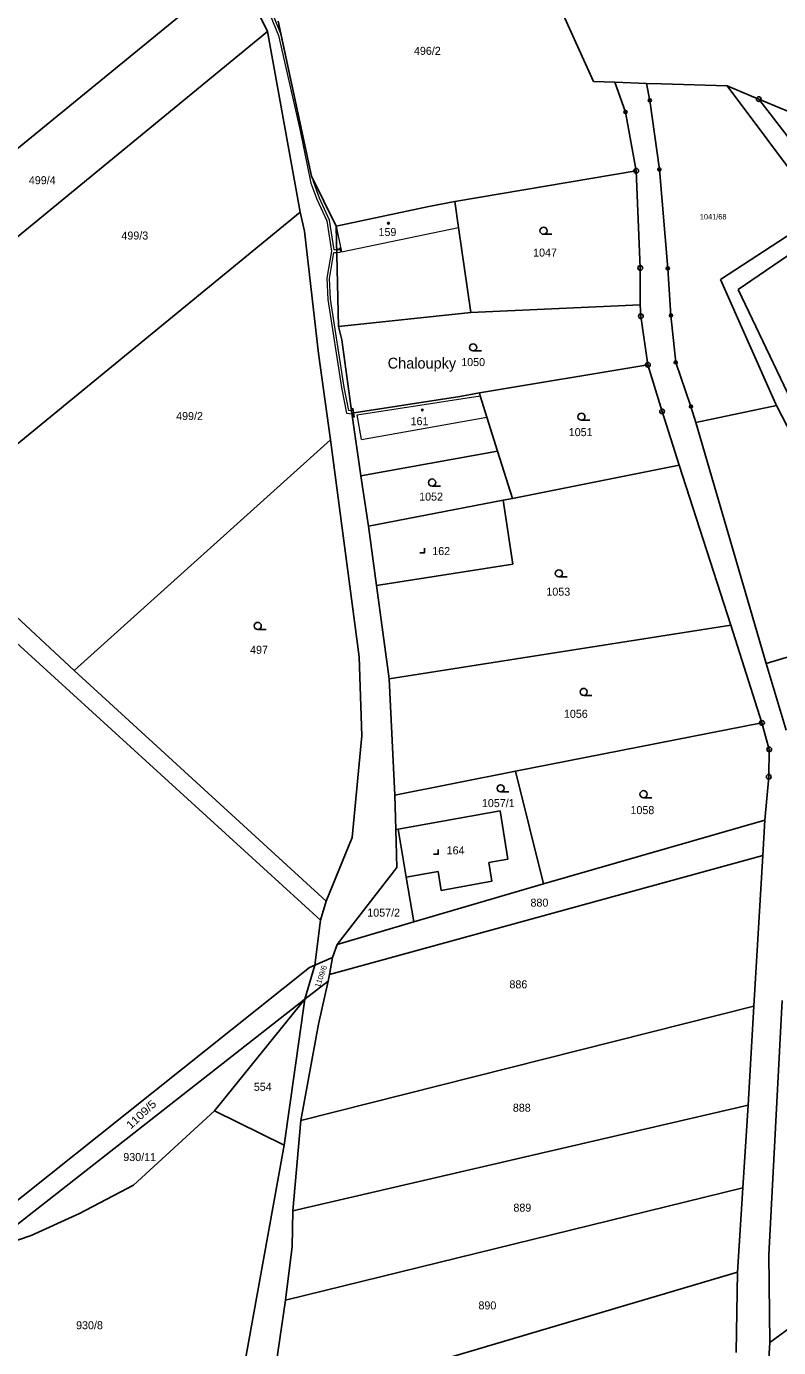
# Model space of a CAD drawing. Extents: x -694609 to -690140, y -1033292 to -1029794.
# Drawn here: x -691085 to -690925.2, y -1031744.2 to -1031463.5 of the extents above; entities that cross this region are included whole.
import ezdxf
from ezdxf.enums import TextEntityAlignment as Align

# ---------------------------------------------------------------- set-up
doc = ezdxf.new("R2010")
doc.units = 0
doc.header["$LTSCALE"] = 0.68
for name, color, linetype, lineweight in [('1', 7, 'Continuous', 25), ('13', 7, 'Continuous', 13), ('3', 7, 'Continuous', 25), ('4', 7, 'Continuous', 13), ('5', 7, 'Continuous', 25), ('7', 7, 'Continuous', 13), ('8', 7, 'Continuous', 25)]:
    doc.layers.add(name, color=color, linetype=linetype, lineweight=lineweight)
doc.layers.add('2', color=7, linetype='Continuous')

msp = doc.modelspace()

# ---------------------------------------------------------------- linework, layer by layer
at = {"layer": '1'}
for p, q in [((-690977.69, -1031446.05), (-690964.56, -1031475.26)), ((-691040.21, -1031451.34), (-691144, -1031536.13)), ((-691033.73, -1031464.62), (-691040.21, -1031451.34)), ((-691024.42, -1031495.33), (-691031.48, -1031462.45)), ((-691033.73, -1031464.62), (-691133.16, -1031546.19)), ((-691026.82, -1031502.98), (-691033.73, -1031464.62)), ((-690964.56, -1031475.26), (-690959.98, -1031475.41)), ((-690957.73, -1031481.73), (-690959.98, -1031475.41)), ((-690959.98, -1031475.41), (-690953.24, -1031475.63)), ((-690952.56, -1031479.25), (-690953.24, -1031475.63)), ((-690953.24, -1031475.63), (-690950.05, -1031475.73)), ((-690950.05, -1031475.73), (-690936.17, -1031476.19)), ((-690915.94, -1031503.17), (-690936.17, -1031476.19)), ((-690936.17, -1031476.19), (-690931, -1031478.34)), ((-690950.54, -1031493.95), (-690952.56, -1031479.25)), ((-690931, -1031478.34), (-690929.43, -1031478.99)), ((-690877.44, -1031546.54), (-690929.43, -1031478.99)), ((-690929.43, -1031478.99), (-690915.12, -1031484.95)), ((-690955.45, -1031494.2), (-690957.73, -1031481.73)), ((-691019.19, -1031506), (-691024.42, -1031495.33)), ((-690993.96, -1031500.75), (-690955.45, -1031494.2)), ((-690955.45, -1031494.2), (-690954.61, -1031514.86)), ((-690948.75, -1031514.94), (-690950.54, -1031493.95)), ((-690999.53, -1031501.76), (-691019.19, -1031506)), ((-690999.53, -1031501.76), (-690993.96, -1031500.75)), ((-690993.17, -1031506.24), (-690993.96, -1031500.75)), ((-691026.82, -1031502.98), (-691108.02, -1031569.55)), ((-691026.82, -1031502.98), (-691025.88, -1031507.05)), ((-690937.57, -1031517.29), (-690915.94, -1031503.17)), ((-691025.88, -1031507.05), (-691022.92, -1031533.04)), ((-691019.19, -1031506), (-691018.67, -1031527.31)), ((-690990.57, -1031524.34), (-690993.17, -1031506.24)), ((-690933.81, -1031519.44), (-690913.87, -1031505.78)), ((-690954.61, -1031514.86), (-690954.58, -1031522.71)), ((-690948.08, -1031524.92), (-690948.75, -1031514.94)), ((-690925.79, -1031543.77), (-690937.57, -1031517.29)), ((-690918.48, -1031551.64), (-690933.81, -1031519.44)), ((-691018.67, -1031527.31), (-690990.57, -1031524.34)), ((-690990.57, -1031524.34), (-690954.58, -1031522.71)), ((-690954.58, -1031522.71), (-690954.47, -1031525.12)), ((-691018.67, -1031527.31), (-691017.94, -1031530.11)), ((-690954.47, -1031525.12), (-690952.96, -1031535.41)), ((-690947.07, -1031534.91), (-690948.08, -1031524.92)), ((-691017.94, -1031530.11), (-691015.86, -1031545.71)), ((-691022.92, -1031533.04), (-691020.4, -1031551.35)), ((-690988.76, -1031541.42), (-690952.96, -1031535.41)), ((-690952.96, -1031535.41), (-690949.96, -1031545.32)), ((-690943.82, -1031544.27), (-690947.07, -1031534.91)), ((-690992.9, -1031542.17), (-690988.76, -1031541.42)), ((-690988.76, -1031541.42), (-690988.57, -1031542.02)), ((-691015.86, -1031545.71), (-690992.9, -1031542.17)), ((-690988.57, -1031542.02), (-690987.15, -1031546.55)), ((-690943.82, -1031544.27), (-690942.82, -1031547.7)), ((-690942.82, -1031547.7), (-690925.64, -1031544.06)), ((-690925.64, -1031544.06), (-690925.79, -1031543.77)), ((-690921.19, -1031552.75), (-690925.64, -1031544.06)), ((-691015.86, -1031545.71), (-691013.95, -1031559.04)), ((-690987.15, -1031546.55), (-690984.89, -1031553.76)), ((-690949.96, -1031545.32), (-690946.34, -1031556.72)), ((-690927.87, -1031598.9), (-690942.82, -1031547.7)), ((-691020.4, -1031551.35), (-691074.82, -1031600.38)), ((-691020.4, -1031551.35), (-691014.32, -1031597.48)), ((-690981.75, -1031563.8), (-690946.34, -1031556.72)), ((-690946.34, -1031556.72), (-690935.35, -1031590.74)), ((-690983.74, -1031564.19), (-690981.75, -1031563.8)), ((-691012.3, -1031569.74), (-690983.74, -1031564.19)), ((-690981.63, -1031577.77), (-690983.74, -1031564.19)), ((-691074.82, -1031600.38), (-691108.02, -1031569.55)), ((-691010.61, -1031582.3), (-691012.3, -1031569.74)), ((-691010.61, -1031582.3), (-690981.63, -1031577.77)), ((-691007.93, -1031602.18), (-691010.61, -1031582.3)), ((-691022.5, -1031653.42), (-691091.18, -1031590.8)), ((-691007.93, -1031602.18), (-690935.35, -1031590.74)), ((-690935.35, -1031590.74), (-690928.74, -1031611.51)), ((-690927.87, -1031598.9), (-690896.83, -1031589.54)), ((-691014.32, -1031597.48), (-691013.71, -1031614.26)), ((-691021.3, -1031649.41), (-691074.82, -1031600.38)), ((-690923.64, -1031613.04), (-690927.87, -1031598.9)), ((-691006.7, -1031626.85), (-691007.93, -1031602.18)), ((-690981.09, -1031621.79), (-690928.74, -1031611.51)), ((-690928.74, -1031611.51), (-690927.19, -1031617.14)), ((-691013.71, -1031614.26), (-691015.8, -1031635.84)), ((-690927.19, -1031617.14), (-690927.29, -1031622.97)), ((-691006.7, -1031626.85), (-690981.09, -1031621.79)), ((-690981.09, -1031621.79), (-690975.11, -1031645.73)), ((-690927.29, -1031622.97), (-690928.12, -1031632.2)), ((-691006.49, -1031634.14), (-691006.7, -1031626.85)), ((-691006.02, -1031634.06), (-690984.34, -1031630.19)), ((-690984.34, -1031630.19), (-690982.71, -1031640.46)), ((-691006.49, -1031634.14), (-691006.02, -1031634.06)), ((-691006.26, -1031642.21), (-691006.49, -1031634.14)), ((-691006.02, -1031634.06), (-691004.28, -1031644.3)), ((-690975.11, -1031645.73), (-690928.12, -1031632.2)), ((-690928.58, -1031639.67), (-690928.12, -1031632.2)), ((-691015.8, -1031635.84), (-691021.3, -1031649.41)), ((-691020.6, -1031664.96), (-690928.58, -1031639.67)), ((-690930.5, -1031671.7), (-690928.58, -1031639.67)), ((-691019, -1031658.56), (-691006.26, -1031642.21)), ((-690986.76, -1031641.18), (-690982.71, -1031640.46)), ((-690986.76, -1031641.18), (-690986.11, -1031645.17)), ((-691004.28, -1031644.3), (-690997.54, -1031643.1)), ((-691004.28, -1031644.3), (-691002.69, -1031653.75)), ((-690997.54, -1031643.1), (-690996.89, -1031647.09)), ((-690996.89, -1031647.09), (-690986.11, -1031645.17)), ((-691002.69, -1031653.75), (-690975.11, -1031645.73)), ((-691022.5, -1031653.42), (-691021.3, -1031649.41)), ((-691023.69, -1031662.97), (-691022.5, -1031653.42)), ((-691019, -1031658.56), (-691002.69, -1031653.75)), ((-691019.93, -1031661.33), (-691019, -1031658.56)), ((-691019.93, -1031661.33), (-691023.69, -1031662.97)), ((-691020.6, -1031664.96), (-691019.93, -1031661.33)), ((-691101.39, -1031724.53), (-691024.87, -1031663.48)), ((-691025.84, -1031670.19), (-691023.69, -1031662.97)), ((-691023.69, -1031662.97), (-691024.87, -1031663.48)), ((-691020.87, -1031666.39), (-691020.6, -1031664.96)), ((-691025.84, -1031670.19), (-691020.87, -1031666.39)), ((-691022.93, -1031675.53), (-691020.87, -1031666.39)), ((-691093.45, -1031723.2), (-691025.84, -1031670.19)), ((-691045, -1031693.97), (-691025.84, -1031670.19)), ((-691030.2, -1031701.21), (-691025.84, -1031670.19)), ((-690927.26, -1031724.52), (-690924.48, -1031670.48)), ((-690930.5, -1031671.7), (-691026.71, -1031696.02)), ((-690931.7, -1031692.76), (-690930.5, -1031671.7)), ((-691026.71, -1031696.02), (-691022.93, -1031675.53)), ((-691028.39, -1031715.21), (-690931.7, -1031692.76)), ((-690932.82, -1031710.26), (-690931.7, -1031692.76)), ((-691045, -1031693.97), (-691062.19, -1031709.74)), ((-691030.2, -1031701.21), (-691045, -1031693.97)), ((-691028.39, -1031715.21), (-691026.71, -1031696.02)), ((-691041.79, -1031765.13), (-691030.2, -1031701.21)), ((-691062.19, -1031709.74), (-691073.72, -1031715.78)), ((-691029.94, -1031734.18), (-690932.82, -1031710.26)), ((-690933.97, -1031728.2), (-690932.82, -1031710.26)), ((-690927.09, -1031743.17), (-690882.73, -1031710.56)), ((-691028.55, -1031722.73), (-691028.39, -1031715.21)), ((-691073.72, -1031715.78), (-691083.94, -1031720.41)), ((-691083.94, -1031720.41), (-691089.14, -1031722.17)), ((-691029.94, -1031734.18), (-691028.55, -1031722.73)), ((-690927.09, -1031743.17), (-690927.26, -1031724.52)), ((-690933.97, -1031728.2), (-691033.42, -1031757.64)), ((-690934.2, -1031745.3), (-690933.97, -1031728.2)), ((-691033.42, -1031757.64), (-691029.94, -1031734.18)), ((-690927.31, -1031746.64), (-690927.09, -1031743.17))]:
    msp.add_line(p, q, dxfattribs=at)
msp.add_lwpolyline([(-691012.3, -1031569.74), (-691013.95, -1031559.04), (-690984.89, -1031553.76), (-690981.75, -1031563.8)], dxfattribs=at)
at = {"layer": '13'}
msp.add_lwpolyline([(-691035.1, -1031456.41), (-691031.4, -1031465.49), (-691026.93, -1031485.34), (-691024.53, -1031496.85), (-691023.29, -1031500.21), (-691021.15, -1031504.87), (-691020.19, -1031511.3), (-691021.19, -1031517.02), (-691020.95, -1031521.52), (-691018.06, -1031540.28), (-691017.01, -1031545.7), (-691015.84, -1031545.85), (-691015.92, -1031545.24), (-691016.51, -1031545.16), (-691017.46, -1031540.18), (-691020.35, -1031521.46), (-691020.59, -1031517.06), (-691019.64, -1031511.6), (-691019.05, -1031511.56), (-691019.07, -1031511.02), (-691019.63, -1031511), (-691020.57, -1031504.69), (-691022.73, -1031499.99), (-691023.95, -1031496.69), (-691024.1, -1031495.99), (-691024.42, -1031495.33), (-691030.91, -1031465.09), (-691033.62, -1031458.46)], dxfattribs=at)
for points in [[(-691019.07, -1031511.02), (-691019.05, -1031511.56), (-691018.42, -1031511.51), (-691018.19, -1031511.46), (-691018.39, -1031510.68), (-691018.61, -1031510.74), (-691018.54, -1031511.03)], [(-691015.92, -1031545.24), (-691015.84, -1031545.85), (-691015.62, -1031545.88), (-691015.52, -1031546.49), (-691015.27, -1031546.45), (-691015.4, -1031545.64), (-691015.55, -1031544.74), (-691015.79, -1031544.78), (-691015.71, -1031545.26)]]:
    msp.add_lwpolyline(points, close=True, dxfattribs=at)
at = {"layer": '3'}
for p, q in [((-690975.143, -1031507.7), (-690973.393, -1031507.7)), ((-690990.083, -1031532.48), (-690988.333, -1031532.48)), ((-690967.083, -1031547.21), (-690965.333, -1031547.21)), ((-690998.793, -1031561.19), (-690997.043, -1031561.19)), ((-690971.883, -1031580.5), (-690970.133, -1031580.5)), ((-691035.823, -1031591.65), (-691034.073, -1031591.65)), ((-690966.603, -1031605.67), (-690964.853, -1031605.67)), ((-690984.253, -1031626.17), (-690982.503, -1031626.17)), ((-690953.903, -1031627.41), (-690952.153, -1031627.41))]:
    msp.add_line(p, q, dxfattribs=at)
for points in [[(-691001.411, -1031575.37), (-691000.41, -1031575.37), (-691000.41, -1031574.37)], [(-690998.491, -1031639.41), (-690997.49, -1031639.41), (-690997.49, -1031638.41)]]:
    msp.add_lwpolyline(points, dxfattribs=at)
for centre in [(-690975.1429, -1031506.9498), (-690990.0829, -1031531.7298), (-690967.0829, -1031546.4598), (-690998.7929, -1031560.4398), (-690971.8829, -1031579.7498), (-691035.8229, -1031590.8998), (-690966.6029, -1031604.9198), (-690984.2529, -1031625.4198), (-690953.9029, -1031626.6598)]:
    msp.add_circle(centre, 0.75, dxfattribs=at)
at = {"layer": '4'}
for p, q in [((-691019.19, -1031506), (-691018.04, -1031511.44)), ((-691018.04, -1031511.44), (-690993.17, -1031506.24)), ((-691014.73, -1031546.07), (-690988.57, -1031542.02)), ((-691013.77, -1031551.31), (-691014.73, -1031546.07)), ((-691013.77, -1031551.31), (-690987.15, -1031546.55))]:
    msp.add_line(p, q, dxfattribs=at)
at = {"layer": '5'}
for centre in [(-691008.0668, -1031505.3392), (-691000.8668, -1031545.0492)]:
    msp.add_circle(centre, 0.175, dxfattribs=at)
at = {"layer": '8'}
for centre, radius in [((-690952.56, -1031479.2499), 0.335), ((-690952.56, -1031479.2499), 0.0203), ((-690929.43, -1031478.9899), 0.5), ((-690929.43, -1031478.9899), 0.0303), ((-690957.73, -1031481.7299), 0.335), ((-690957.73, -1031481.7299), 0.0203), ((-690955.45, -1031494.1999), 0.5), ((-690950.54, -1031493.9499), 0.335), ((-690955.45, -1031494.1999), 0.0303), ((-690950.54, -1031493.9499), 0.0203), ((-690954.61, -1031514.8599), 0.5), ((-690954.61, -1031514.8599), 0.0303), ((-690948.75, -1031514.9399), 0.335), ((-690948.75, -1031514.9399), 0.0203), ((-690954.47, -1031525.1199), 0.5), ((-690948.08, -1031524.9199), 0.335), ((-690954.47, -1031525.1199), 0.0303), ((-690948.08, -1031524.9199), 0.0203), ((-690952.96, -1031535.4099), 0.5), ((-690952.96, -1031535.4099), 0.0303), ((-690947.07, -1031534.9099), 0.335), ((-690947.07, -1031534.9099), 0.0203), ((-690943.82, -1031544.2699), 0.335), ((-690943.82, -1031544.2699), 0.0203), ((-690949.96, -1031545.3199), 0.5), ((-690949.96, -1031545.3199), 0.0303), ((-690928.74, -1031611.5099), 0.5), ((-690928.74, -1031611.5099), 0.0303), ((-690927.19, -1031617.1399), 0.5), ((-690927.19, -1031617.1399), 0.0303), ((-690927.29, -1031622.9699), 0.5), ((-690927.29, -1031622.9699), 0.0303)]:
    msp.add_circle(centre, radius, dxfattribs=at)

# ---------------------------------------------------------------- texts
at = {"layer": '2'}
for s, height, p in [('496/2', 1.7, (-690999.81, -1031469.575)), ('499/4', 1.7, (-691081.6, -1031497.055)), ('1041/68', 1.14, (-690939.11, -1031504.545)), ('499/3', 1.7, (-691061.94, -1031508.815)), ('159', 1.7, (-691008.289, -1031508.075)), ('1047', 1.7, (-690974.82, -1031512.435)), ('1050', 1.7, (-690990.09, -1031535.705)), ('499/2', 1.7, (-691050.32, -1031547.165)), ('161', 1.7, (-691001.469, -1031548.255)), ('1051', 1.7, (-690967.25, -1031550.585)), ('1052', 1.7, (-690999.02, -1031564.285)), ('162', 1.7, (-690996.869, -1031575.855)), ('1053', 1.7, (-690972, -1031584.485)), ('497', 1.7, (-691035.559, -1031596.825)), ('1056', 1.7, (-690968.28, -1031610.435)), ('1057/1', 1.7, (-690984.75, -1031629.405)), ('1058', 1.7, (-690954.14, -1031630.895)), ('164', 1.7, (-690993.819, -1031639.445)), ('1057/2', 1.7, (-691009.09, -1031652.675)), ('880', 1.7, (-690976.009, -1031650.555)), ('886', 1.7, (-690980.479, -1031667.905)), ('554', 1.7, (-691034.769, -1031689.685)), ('888', 1.7, (-690979.759, -1031694.125)), ('930/11', 1.7, (-691060.91, -1031704.605)), ('889', 1.7, (-690979.639, -1031715.355)), ('890', 1.7, (-690987.059, -1031736.125)), ('930/8', 1.7, (-691071.57, -1031740.335))]:
    msp.add_text(s, height=height, dxfattribs=at).set_placement(p, align=Align.CENTER)
msp.add_text('1109/6', height=1.14, rotation=71, dxfattribs=at).set_placement((-691021.8777, -1031665.5676), align=Align.CENTER)
at = {"layer": '2', "width": 1.1}
msp.add_text('1109/5', height=1.7, rotation=43, dxfattribs=at).set_placement((-691059.9947, -1031695.3047), align=Align.CENTER)
at = {"layer": '7'}
msp.add_text('Chaloupky', height=2.3, dxfattribs=at).set_placement((-691000.97, -1031536.225), align=Align.CENTER)

doc.saveas('drawing.dxf')
